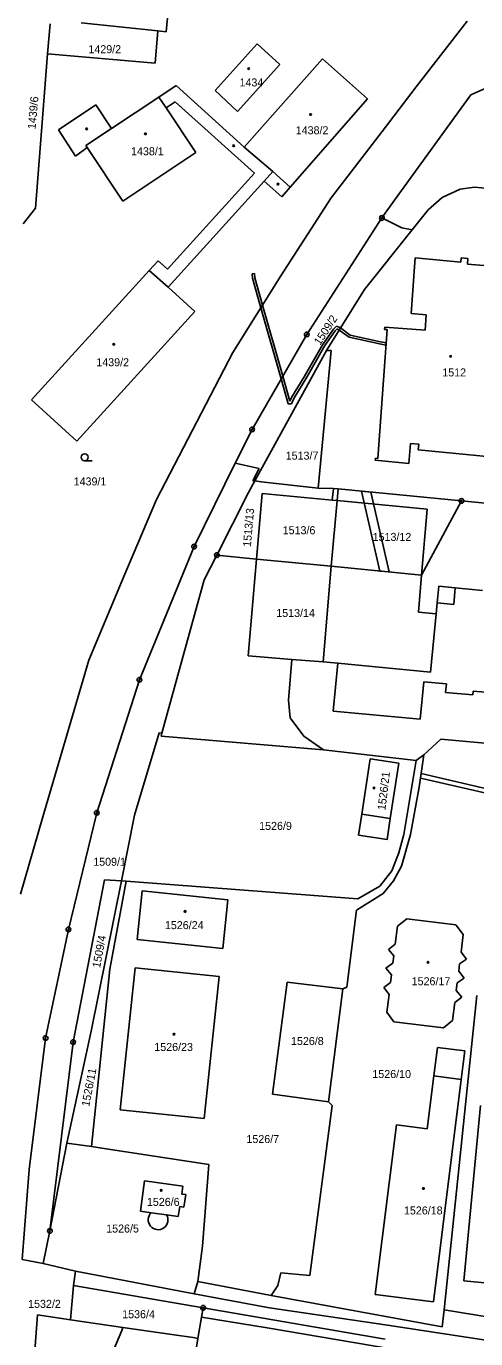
# Model space of a CAD drawing. Extents: x -755819 to -753140, y -1169796 to -1166000.
# Drawn here: x -755557.5 to -755462, y -1167599.3 to -1167320.5 of the extents above; entities that cross this region are included whole.
import ezdxf

# ---------------------------------------------------------------- set-up
doc = ezdxf.new("R2010")
doc.units = 0
for name, color, linetype in [('Vrstva 1', 7, 'Continuous'), ('Vrstva 18', 7, 'Continuous'), ('Vrstva 19', 7, 'Continuous'), ('Vrstva 24', 7, 'Continuous'), ('Vrstva 25', 7, 'Continuous'), ('Vrstva 27', 7, 'Continuous'), ('Vrstva 4', 7, 'Continuous'), ('Vrstva 6', 7, 'Continuous')]:
    doc.layers.add(name, color=color, linetype=linetype)

msp = doc.modelspace()

# ---------------------------------------------------------------- linework, layer by layer
at = {"layer": 'Vrstva 1'}
for p, q in [((-755527, -1167313.51), (-755527.77, -1167321.67)), ((-755552.45, -1167319.97), (-755553.02, -1167326.32)), ((-755545.87, -1167319.76), (-755529.57, -1167321.48)), ((-755474.62, -1167333.33), (-755463.78, -1167319.39)), ((-755530.15, -1167328.33), (-755529.57, -1167321.48)), ((-755527.77, -1167321.67), (-755529.57, -1167321.48)), ((-755517.37, -1167334.13), (-755508.43, -1167324.19)), ((-755508.43, -1167324.19), (-755503.65, -1167328.62)), ((-755555.56, -1167359.13), (-755553.02, -1167326.32)), ((-755553.02, -1167326.32), (-755530.15, -1167328.33)), ((-755503.65, -1167328.62), (-755512.63, -1167338.62)), ((-755511.22, -1167346.17), (-755494.53, -1167327.42)), ((-755494.53, -1167327.42), (-755484.97, -1167335.87)), ((-755525.65, -1167333.1), (-755529.33, -1167335.55)), ((-755525.65, -1167333.1), (-755511.22, -1167346.17)), ((-755512.63, -1167338.62), (-755517.37, -1167334.13)), ((-755474.62, -1167333.33), (-755481.9, -1167342.83)), ((-755463.04, -1167335.03), (-755459.81, -1167333.64)), ((-755550.68, -1167342.51), (-755542.75, -1167337.15)), ((-755542.75, -1167337.15), (-755539.38, -1167342.21)), ((-755539.38, -1167342.21), (-755529.33, -1167335.55)), ((-755527.82, -1167337.82), (-755525.86, -1167336.51)), ((-755508.98, -1167351.73), (-755525.86, -1167336.51)), ((-755484.97, -1167335.87), (-755501.41, -1167354.64)), ((-755479.25, -1167357.44), (-755463.04, -1167335.03)), ((-755521.5, -1167347.28), (-755527.82, -1167337.82)), ((-755547.05, -1167348.08), (-755550.68, -1167342.51)), ((-755481.9, -1167342.83), (-755492.71, -1167356.96)), ((-755547.05, -1167348.08), (-755544.59, -1167346.23)), ((-755544.59, -1167346.23), (-755536.98, -1167357.61)), ((-755536.98, -1167357.61), (-755521.5, -1167347.28)), ((-755505.15, -1167351.31), (-755511.22, -1167346.17)), ((-755527.5, -1167372.1), (-755508.98, -1167351.73)), ((-755527.4, -1167375.95), (-755506.96, -1167353.42)), ((-755503.21, -1167356.7), (-755506.96, -1167353.42)), ((-755501.41, -1167354.64), (-755505.15, -1167351.31)), ((-755501.41, -1167354.64), (-755503.21, -1167356.7)), ((-755465.27, -1167355.07), (-755469.13, -1167356.9)), ((-755462.21, -1167354.66), (-755465.27, -1167355.07)), ((-755457.8, -1167355.12), (-755462.21, -1167354.66)), ((-755558.22, -1167362.49), (-755555.56, -1167359.13)), ((-755492.71, -1167356.96), (-755503.39, -1167373.53)), ((-755481.94, -1167361.22), (-755479.25, -1167357.44)), ((-755472.09, -1167359.46), (-755475.53, -1167363.77)), ((-755469.13, -1167356.9), (-755472.09, -1167359.46)), ((-755497.9, -1167385.95), (-755481.94, -1167361.22)), ((-755481.94, -1167361.22), (-755477.72, -1167363.3)), ((-755475.53, -1167363.77), (-755485.62, -1167376.39)), ((-755475.53, -1167363.77), (-755477.72, -1167363.3)), ((-755531.38, -1167372.36), (-755529.5, -1167370.29)), ((-755529.5, -1167370.29), (-755527.5, -1167372.1)), ((-755474.86, -1167369.69), (-755475.7, -1167381.53)), ((-755465.13, -1167370.58), (-755474.86, -1167369.69)), ((-755465.05, -1167369.68), (-755465.13, -1167370.58)), ((-755463.64, -1167369.81), (-755465.05, -1167369.68)), ((-755463.75, -1167371.01), (-755463.64, -1167369.81)), ((-755556.41, -1167399.86), (-755531.38, -1167372.36)), ((-755531.38, -1167372.36), (-755527.4, -1167375.95)), ((-755459.41, -1167371.41), (-755463.75, -1167371.01)), ((-755527.4, -1167375.95), (-755521.71, -1167381.1)), ((-755503.39, -1167373.53), (-755513.59, -1167389.78)), ((-755485.62, -1167376.39), (-755493.69, -1167389.34)), ((-755521.71, -1167381.1), (-755546.76, -1167408.66)), ((-755475.7, -1167381.53), (-755472.53, -1167381.76)), ((-755472.53, -1167381.76), (-755472.76, -1167385.06)), ((-755481.33, -1167384.45), (-755481.36, -1167384.88)), ((-755472.76, -1167385.06), (-755481.33, -1167384.45)), ((-755509.52, -1167406.14), (-755497.9, -1167385.95)), ((-755480.82, -1167384.91), (-755482.77, -1167412.32)), ((-755481.36, -1167384.88), (-755480.82, -1167384.91)), ((-755513.59, -1167389.78), (-755529.84, -1167421.04)), ((-755508.96, -1167417.09), (-755493.69, -1167389.34)), ((-755495.46, -1167418.62), (-755492.69, -1167389.35)), ((-755492.69, -1167389.35), (-755493.69, -1167389.34)), ((-755546.76, -1167408.66), (-755556.41, -1167399.86)), ((-755509.52, -1167406.14), (-755513.09, -1167413.34)), ((-755476.23, -1167413.37), (-755475.82, -1167409.12)), ((-755475.82, -1167409.12), (-755474.09, -1167409.28)), ((-755474.09, -1167409.28), (-755474.21, -1167410.51)), ((-755483.31, -1167412.28), (-755483.34, -1167412.7)), ((-755482.77, -1167412.32), (-755483.31, -1167412.28)), ((-755474.21, -1167410.51), (-755458.94, -1167411.96)), ((-755513.09, -1167413.34), (-755521.87, -1167431.03)), ((-755483.34, -1167412.7), (-755476.23, -1167413.37)), ((-755508.96, -1167417.09), (-755510.29, -1167419.52)), ((-755509.38, -1167417.05), (-755508.96, -1167417.09)), ((-755508.96, -1167417.09), (-755507.62, -1167417.25)), ((-755495.46, -1167418.62), (-755507.62, -1167417.25)), ((-755510.29, -1167419.52), (-755517.02, -1167432.85)), ((-755507.41, -1167419.79), (-755508.61, -1167433.68)), ((-755507.41, -1167419.79), (-755492.47, -1167421.18)), ((-755492.24, -1167418.69), (-755495.46, -1167418.62)), ((-755492.47, -1167421.18), (-755492.24, -1167418.69)), ((-755491.24, -1167418.78), (-755492.24, -1167418.69)), ((-755491.24, -1167418.78), (-755491.47, -1167421.27)), ((-755491.24, -1167418.78), (-755465.02, -1167421.32)), ((-755529.84, -1167421.04), (-755536.81, -1167437.36)), ((-755491.47, -1167421.27), (-755492.68, -1167435.23)), ((-755473.48, -1167437.1), (-755465.02, -1167421.32)), ((-755465.02, -1167421.32), (-755459.97, -1167421.81)), ((-755521.87, -1167431.03), (-755533.49, -1167459.33)), ((-755517.02, -1167432.85), (-755519.68, -1167438.12)), ((-755517.02, -1167432.85), (-755508.61, -1167433.68)), ((-755508.61, -1167433.68), (-755510.38, -1167454.24)), ((-755508.61, -1167433.68), (-755492.68, -1167435.23)), ((-755536.81, -1167437.36), (-755544.22, -1167455.14)), ((-755492.68, -1167435.23), (-755494.44, -1167455.54)), ((-755492.68, -1167435.23), (-755473.48, -1167437.1)), ((-755519.68, -1167438.12), (-755528.7, -1167470.66)), ((-755469.81, -1167439.48), (-755470.15, -1167443)), ((-755469.81, -1167439.48), (-755466.32, -1167439.82)), ((-755460.56, -1167440.38), (-755466.32, -1167439.82)), ((-755470.37, -1167445.29), (-755470.15, -1167443)), ((-755471.58, -1167457.71), (-755470.37, -1167445.29)), ((-755510.38, -1167454.24), (-755501.06, -1167455)), ((-755544.22, -1167455.14), (-755549.25, -1167472.3)), ((-755494.44, -1167455.54), (-755501.06, -1167455)), ((-755492.26, -1167465.97), (-755491.27, -1167455.8)), ((-755491.27, -1167455.8), (-755471.58, -1167457.71)), ((-755533.49, -1167459.33), (-755542.54, -1167487.58)), ((-755473.01, -1167459.75), (-755473.76, -1167467.7)), ((-755468.21, -1167460.2), (-755473.01, -1167459.75)), ((-755468.38, -1167462.01), (-755468.21, -1167460.2)), ((-755462.6, -1167462.55), (-755468.38, -1167462.01)), ((-755462.52, -1167461.72), (-755462.6, -1167462.55)), ((-755457.53, -1167462.18), (-755462.52, -1167461.72)), ((-755473.76, -1167467.7), (-755492.26, -1167465.97)), ((-755529.3, -1167470.6), (-755534.52, -1167488.11)), ((-755529.3, -1167470.6), (-755528.7, -1167470.66)), ((-755528.87, -1167471.28), (-755528.7, -1167470.66)), ((-755549.25, -1167472.3), (-755553.99, -1167488.43)), ((-755494.36, -1167474.25), (-755528.87, -1167471.28)), ((-755473.05, -1167475.25), (-755469.39, -1167471.94)), ((-755456.18, -1167473.17), (-755469.39, -1167471.94)), ((-755494.36, -1167474.25), (-755474.67, -1167476.47)), ((-755486.21, -1167487.91), (-755484.39, -1167476.14)), ((-755484.39, -1167476.14), (-755478.35, -1167477.07)), ((-755474.67, -1167476.47), (-755477.27, -1167492.2)), ((-755474.67, -1167476.47), (-755473.05, -1167475.25)), ((-755474.01, -1167482.12), (-755473.05, -1167475.25)), ((-755478.35, -1167477.07), (-755480.16, -1167488.84)), ((-755475.84, -1167492.24), (-755474.01, -1167482.12)), ((-755542.54, -1167487.58), (-755548.56, -1167512.37)), ((-755553.99, -1167488.43), (-755558.78, -1167504.92)), ((-755537.31, -1167502.05), (-755534.52, -1167488.11)), ((-755486.9, -1167492.35), (-755486.21, -1167487.91)), ((-755480.16, -1167488.84), (-755480.84, -1167493.28)), ((-755480.84, -1167493.28), (-755486.9, -1167492.35)), ((-755477.27, -1167492.2), (-755478.36, -1167496.09)), ((-755477.78, -1167498.96), (-755475.84, -1167492.24)), ((-755478.36, -1167496.09), (-755479.85, -1167499.93)), ((-755479.46, -1167502.07), (-755477.78, -1167498.96)), ((-755479.85, -1167499.93), (-755482.4, -1167503.22)), ((-755540.87, -1167501.82), (-755547.57, -1167536.3)), ((-755543.71, -1167533.97), (-755537.31, -1167502.05)), ((-755540.87, -1167501.82), (-755537.31, -1167502.05)), ((-755536.31, -1167502.11), (-755539.77, -1167520.82)), ((-755536.31, -1167502.11), (-755537.31, -1167502.05)), ((-755487.04, -1167505.87), (-755536.31, -1167502.11)), ((-755533.96, -1167514.54), (-755532.9, -1167504.18)), ((-755532.9, -1167504.18), (-755514.65, -1167506.06)), ((-755482.4, -1167503.22), (-755487.04, -1167505.87)), ((-755481.66, -1167504.72), (-755479.46, -1167502.07)), ((-755514.65, -1167506.06), (-755515.72, -1167516.44)), ((-755487.35, -1167508.28), (-755481.66, -1167504.72)), ((-755489.36, -1167524.68), (-755487.35, -1167508.28)), ((-755478.62, -1167511.68), (-755476.64, -1167510.11)), ((-755476.64, -1167510.11), (-755466.23, -1167511.42)), ((-755548.56, -1167512.37), (-755553.41, -1167535.46)), ((-755479.09, -1167515.49), (-755478.62, -1167511.68)), ((-755466.23, -1167511.42), (-755464.64, -1167513.44)), ((-755515.72, -1167516.44), (-755533.96, -1167514.54)), ((-755480.55, -1167516.63), (-755479.09, -1167515.49)), ((-755464.64, -1167513.44), (-755465.1, -1167517.22)), ((-755479.4, -1167518), (-755480.55, -1167516.63)), ((-755479.59, -1167519.54), (-755479.4, -1167518)), ((-755465.1, -1167517.22), (-755463.95, -1167518.67)), ((-755539.77, -1167520.82), (-755543.66, -1167558.48)), ((-755537.57, -1167550.69), (-755534.39, -1167520.51)), ((-755534.39, -1167520.51), (-755516.55, -1167522.4)), ((-755481.06, -1167520.64), (-755479.59, -1167519.54)), ((-755479.9, -1167522.03), (-755481.06, -1167520.64)), ((-755465.41, -1167519.7), (-755465.6, -1167521.26)), ((-755465.6, -1167521.26), (-755464.45, -1167522.72)), ((-755463.95, -1167518.67), (-755465.41, -1167519.7)), ((-755516.55, -1167522.4), (-755519.73, -1167552.57)), ((-755502.1, -1167523.56), (-755505.17, -1167547.36)), ((-755490.23, -1167525), (-755502.1, -1167523.56)), ((-755481.55, -1167524.72), (-755480.1, -1167523.62)), ((-755480.1, -1167523.62), (-755479.9, -1167522.03)), ((-755465.91, -1167523.75), (-755466.11, -1167525.34)), ((-755464.45, -1167522.72), (-755465.91, -1167523.75)), ((-755493.27, -1167549.02), (-755490.23, -1167525)), ((-755490.23, -1167525), (-755489.36, -1167524.68)), ((-755480.42, -1167526.19), (-755481.55, -1167524.72)), ((-755480.89, -1167529.99), (-755480.42, -1167526.19)), ((-755461.74, -1167526.4), (-755468.72, -1167593.21)), ((-755464.96, -1167526.8), (-755466.42, -1167527.92)), ((-755466.11, -1167525.34), (-755464.96, -1167526.8)), ((-755466.42, -1167527.92), (-755466.89, -1167531.71)), ((-755479.36, -1167531.99), (-755480.89, -1167529.99)), ((-755468.81, -1167533.29), (-755479.36, -1167531.99)), ((-755466.89, -1167531.71), (-755468.81, -1167533.29)), ((-755548.92, -1167557.77), (-755543.71, -1167533.97)), ((-755553.41, -1167535.46), (-755556.91, -1167563.38)), ((-755552.5, -1167576.44), (-755547.57, -1167536.3)), ((-755470.88, -1167543.5), (-755470.11, -1167537.46)), ((-755470.11, -1167537.46), (-755464.3, -1167538.19)), ((-755464.3, -1167538.19), (-755465.05, -1167544.23)), ((-755472.32, -1167554.76), (-755470.88, -1167543.5)), ((-755465.05, -1167544.23), (-755470.96, -1167591.51)), ((-755505.17, -1167547.36), (-755493.27, -1167549.02)), ((-755492.53, -1167549.78), (-755493.27, -1167549.02)), ((-755519.73, -1167552.57), (-755537.57, -1167550.69)), ((-755497.23, -1167585.93), (-755492.53, -1167549.78)), ((-755460.94, -1167549.8), (-755464.48, -1167587.07)), ((-755483.38, -1167589.95), (-755478.85, -1167553.91)), ((-755478.85, -1167553.91), (-755472.32, -1167554.76)), ((-755552.5, -1167576.44), (-755548.92, -1167557.77)), ((-755548.92, -1167557.77), (-755543.66, -1167558.48)), ((-755543.66, -1167558.48), (-755540.56, -1167558.96)), ((-755518.72, -1167562.33), (-755540.56, -1167558.96)), ((-755518.72, -1167562.33), (-755520.04, -1167579.69)), ((-755556.91, -1167563.38), (-755558.38, -1167582.5)), ((-755532.42, -1167565.78), (-755533.28, -1167572.27)), ((-755524.24, -1167566.91), (-755532.42, -1167565.78)), ((-755524.48, -1167568.6), (-755524.24, -1167566.91)), ((-755523.59, -1167568.72), (-755524.48, -1167568.6)), ((-755525.21, -1167573.34), (-755524.87, -1167571.27)), ((-755524.87, -1167571.27), (-755524.01, -1167571.37)), ((-755524.01, -1167571.37), (-755523.59, -1167568.72)), ((-755533.28, -1167572.27), (-755530.98, -1167572.57)), ((-755530.98, -1167572.57), (-755527.71, -1167573)), ((-755525.21, -1167573.34), (-755527.71, -1167573)), ((-755553.95, -1167583.39), (-755552.5, -1167576.44)), ((-755520.04, -1167579.69), (-755521.05, -1167587.15)), ((-755558.38, -1167582.5), (-755553.95, -1167583.39)), ((-755553.95, -1167583.39), (-755547.1, -1167584.97)), ((-755547.1, -1167584.97), (-755547.47, -1167588)), ((-755521.82, -1167589.77), (-755547.1, -1167584.97)), ((-755504.03, -1167588.05), (-755503.38, -1167585.31)), ((-755503.38, -1167585.31), (-755497.23, -1167585.93)), ((-755548.1, -1167595.3), (-755547.47, -1167588)), ((-755519.94, -1167592.75), (-755547.47, -1167588)), ((-755521.05, -1167587.15), (-755521.82, -1167589.77)), ((-755521.05, -1167587.15), (-755505.48, -1167590.19)), ((-755505.48, -1167590.19), (-755504.03, -1167588.05)), ((-755464.48, -1167587.07), (-755386.77, -1167594.44)), ((-755505.85, -1167592.8), (-755521.82, -1167589.77)), ((-755505.48, -1167590.19), (-755469.09, -1167596.79)), ((-755470.96, -1167591.51), (-755483.38, -1167589.95)), ((-755520.28, -1167594.78), (-755519.94, -1167592.75)), ((-755519.94, -1167592.75), (-755481.22, -1167599.43)), ((-755480.75, -1167596.47), (-755505.85, -1167592.8)), ((-755469.09, -1167596.79), (-755468.72, -1167593.21)), ((-755468.72, -1167593.21), (-755356.83, -1167611.26)), ((-755559.69, -1167655.67), (-755555.16, -1167594.27)), ((-755548.1, -1167595.3), (-755555.16, -1167594.27)), ((-755536.99, -1167596.92), (-755548.1, -1167595.3)), ((-755520.28, -1167594.78), (-755521.03, -1167599.26)), ((-755520.28, -1167594.78), (-755506.35, -1167597.04)), ((-755480.75, -1167596.47), (-755357.51, -1167615.38)), ((-755542.91, -1167610.91), (-755537.2, -1167597.6)), ((-755537.2, -1167597.6), (-755536.99, -1167596.92)), ((-755536.99, -1167596.92), (-755526.07, -1167598.52)), ((-755526.07, -1167598.52), (-755522.03, -1167599.11)), ((-755522.03, -1167599.11), (-755521.03, -1167599.26)), ((-755521.03, -1167599.26), (-755521.8, -1167603.88)), ((-755472.54, -1167602.78), (-755506.35, -1167597.04))]:
    msp.add_line(p, q, dxfattribs=at)
at = {"layer": 'Vrstva 24'}
for centre, radius in [((-755481.94, -1167361.22), 0.5), ((-755481.94, -1167361.22), 0.1), ((-755497.9, -1167385.95), 0.5), ((-755497.9, -1167385.95), 0.1), ((-755509.52, -1167406.14), 0.5), ((-755509.52, -1167406.14), 0.1), ((-755465.02, -1167421.32), 0.5), ((-755465.02, -1167421.32), 0.1), ((-755521.87, -1167431.03), 0.5), ((-755521.87, -1167431.03), 0.1), ((-755517.02, -1167432.85), 0.5), ((-755517.02, -1167432.85), 0.1), ((-755533.49, -1167459.33), 0.5), ((-755533.49, -1167459.33), 0.1), ((-755542.54, -1167487.58), 0.5), ((-755542.54, -1167487.58), 0.1), ((-755548.56, -1167512.37), 0.5), ((-755548.56, -1167512.37), 0.1), ((-755553.41, -1167535.46), 0.5), ((-755553.41, -1167535.46), 0.1), ((-755547.57, -1167536.3), 0.5), ((-755547.57, -1167536.3), 0.1), ((-755552.5, -1167576.44), 0.5), ((-755552.5, -1167576.44), 0.1), ((-755519.94, -1167592.75), 0.5), ((-755519.94, -1167592.75), 0.1)]:
    msp.add_circle(centre, radius, dxfattribs=at)
at = {"layer": 'Vrstva 25'}
msp.add_line((-755545.12, -1167412.81), (-755543.52, -1167412.81), dxfattribs=at)
for centre, radius in [((-755510.26, -1167329.51), 0.175), ((-755497.1, -1167339.23), 0.175), ((-755544.71, -1167342.29), 0.175), ((-755532.2, -1167343.34), 0.175), ((-755513.43, -1167345.88), 0.175), ((-755504, -1167354.02), 0.175), ((-755538.92, -1167388.08), 0.175), ((-755467.3, -1167390.63), 0.175), ((-755545.12, -1167412.06), 0.75), ((-755483.62, -1167482.33), 0.175), ((-755523.76, -1167508.56), 0.175), ((-755472.13, -1167519.36), 0.175), ((-755526.12, -1167534.64), 0.175), ((-755528.84, -1167567.81), 0.175), ((-755473.1, -1167567.42), 0.175)]:
    msp.add_circle(centre, radius, dxfattribs=at)
at = {"layer": 'Vrstva 27'}
for p, q in [((-755509.53, -1167373.05), (-755509.03, -1167373)), ((-755509.43, -1167374), (-755509.53, -1167373.05)), ((-755509.03, -1167373), (-755508.93, -1167373.92)), ((-755507.64, -1167380.3), (-755509.43, -1167374)), ((-755508.93, -1167373.92), (-755507.28, -1167379.73)), ((-755507.28, -1167379.73), (-755507.64, -1167380.3)), ((-755507.64, -1167380.3), (-755507.28, -1167379.73)), ((-755503.35, -1167395.41), (-755507.64, -1167380.3)), ((-755507.28, -1167379.73), (-755503, -1167394.81)), ((-755492.19, -1167384.86), (-755491.59, -1167384.22)), ((-755491.59, -1167384.22), (-755490.86, -1167384.46)), ((-755490.72, -1167384.57), (-755491.04, -1167385.08)), ((-755491.04, -1167385.08), (-755490.72, -1167384.57)), ((-755490.86, -1167384.46), (-755490.72, -1167384.57)), ((-755490.72, -1167384.57), (-755488.68, -1167386.09)), ((-755494.54, -1167388.17), (-755492.19, -1167384.86)), ((-755491.83, -1167385.21), (-755494.05, -1167388.33)), ((-755491.45, -1167384.8), (-755491.83, -1167385.21)), ((-755491.04, -1167385.08), (-755491.45, -1167384.8)), ((-755488.91, -1167386.54), (-755491.04, -1167385.08)), ((-755482.09, -1167388.05), (-755488.91, -1167386.54)), ((-755488.68, -1167386.09), (-755482.22, -1167387.52)), ((-755498.45, -1167395), (-755494.54, -1167388.17)), ((-755494.05, -1167388.33), (-755497.89, -1167395.02)), ((-755482.22, -1167387.52), (-755481.02, -1167387.74)), ((-755481.06, -1167388.24), (-755482.09, -1167388.05)), ((-755481.02, -1167387.74), (-755481.06, -1167388.24)), ((-755503.35, -1167395.41), (-755503, -1167394.81)), ((-755503, -1167394.81), (-755503.35, -1167395.41)), ((-755501.84, -1167400.72), (-755503.35, -1167395.41)), ((-755503, -1167394.81), (-755501.47, -1167400.17)), ((-755501.13, -1167399.39), (-755498.45, -1167395)), ((-755497.89, -1167395.02), (-755500.67, -1167399.57)), ((-755501.17, -1167400.72), (-755501.84, -1167400.72)), ((-755501.47, -1167400.17), (-755501.13, -1167399.39)), ((-755500.67, -1167399.57), (-755501.17, -1167400.72)), ((-755482.34, -1167436.24), (-755486.25, -1167419.26)), ((-755486.25, -1167419.26), (-755484.26, -1167419.46)), ((-755484.26, -1167419.46), (-755480.35, -1167436.43)), ((-755480.35, -1167436.43), (-755482.34, -1167436.24)), ((-755473.75, -1167480.26), (-755473.61, -1167479.28)), ((-755473.61, -1167479.28), (-755457.21, -1167483.06)), ((-755457.31, -1167484.02), (-755473.75, -1167480.26))]:
    msp.add_line(p, q, dxfattribs=at)
at = {"layer": 'Vrstva 4'}
for p, q in [((-755527.82, -1167337.82), (-755529.33, -1167335.55)), ((-755539.38, -1167342.21), (-755544.84, -1167345.85)), ((-755544.84, -1167345.85), (-755544.59, -1167346.23)), ((-755506.96, -1167353.42), (-755505.15, -1167351.31)), ((-755492.47, -1167421.18), (-755491.47, -1167421.27)), ((-755491.47, -1167421.27), (-755472.34, -1167423.05)), ((-755472.34, -1167423.05), (-755473.48, -1167437.1)), ((-755473.48, -1167437.1), (-755474.12, -1167444.99)), ((-755466.66, -1167443.33), (-755466.32, -1167439.82)), ((-755470.15, -1167443), (-755466.66, -1167443.33)), ((-755474.12, -1167444.99), (-755470.37, -1167445.29)), ((-755501.06, -1167455), (-755501.77, -1167463.67)), ((-755494.44, -1167455.54), (-755491.27, -1167455.8)), ((-755501.77, -1167463.67), (-755501.42, -1167467.42)), ((-755501.42, -1167467.42), (-755498.5, -1167471.32)), ((-755498.5, -1167471.32), (-755494.36, -1167474.25)), ((-755480.16, -1167488.84), (-755486.21, -1167487.91)), ((-755470.88, -1167543.5), (-755465.05, -1167544.23))]:
    msp.add_line(p, q, dxfattribs=at)
msp.add_arc((-755529.51, -1167574.08), 2.1, 134.2018, 30.8155, dxfattribs=at)
at = {"layer": 'Vrstva 6'}
for p, q in [((-755513.09, -1167413.34), (-755508.01, -1167414.42)), ((-755508.01, -1167414.42), (-755509.38, -1167417.05))]:
    msp.add_line(p, q, dxfattribs=at)

# ---------------------------------------------------------------- texts
at = {"layer": 'Vrstva 18'}
for s, p in [('1429/2', (-755544.32, -1167326.2)), ('1513/7', (-755502.38, -1167412.56)), ('1439/1', (-755547.46, -1167418.04)), ('1513/6', (-755503.02, -1167428.41)), ('1513/12', (-755483.9, -1167429.83)), ('1513/14', (-755504.39, -1167446)), ('1526/9', (-755508.02, -1167491.23)), ('1509/1', (-755543.3, -1167498.85)), ('1526/8', (-755501.25, -1167536.93)), ('1526/10', (-755483.96, -1167543.95)), ('1526/7', (-755510.73, -1167557.76)), ('1526/5', (-755540.54, -1167576.78)), ('1532/2', (-755557.14, -1167592.78)), ('1536/4', (-755537.14, -1167594.98))]:
    msp.add_text(s, height=1.7, dxfattribs=at).set_placement(p)
for s, rotation, p in [('1439/6', 84.7978, (-755555.56, -1167342.4)), ('1509/2', 56.7228, (-755495.09, -1167388.39)), ('1513/13', 85.0842, (-755509.79, -1167431.14)), ('1509/4', 79.1828, (-755541.85, -1167520.65)), ('1526/11', 79.1828, (-755544.15, -1167550.11))]:
    msp.add_text(s, height=1.7, rotation=rotation, dxfattribs=at).set_placement(p)
at = {"layer": 'Vrstva 19'}
for s, p in [('1434', (-755512.2, -1167333.27)), ('1438/2', (-755500.25, -1167343.43)), ('1438/1', (-755535.26, -1167347.89)), ('1439/2', (-755542.64, -1167392.72)), ('1512', (-755469.09, -1167394.88)), ('1526/24', (-755528.06, -1167512.32)), ('1526/17', (-755475.6, -1167524.24)), ('1526/23', (-755530.31, -1167538.2)), ('1526/6', (-755531.89, -1167571.12)), ('1526/18', (-755477.24, -1167572.93))]:
    msp.add_text(s, height=1.7, dxfattribs=at).set_placement(p)
msp.add_text('1526/21', height=1.7, rotation=83.1362, dxfattribs=at).set_placement((-755481.19, -1167487.12))

doc.saveas('drawing.dxf')
